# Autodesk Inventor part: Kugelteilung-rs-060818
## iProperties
Manager: Dr.-Ing. Roland Schröder
Company: www.Das-Entwicklungsbuero.de
Created: 2006-08
Part Number: Kugelteilung-rs-060818
Project: 11307
Document SubType Name: Modeling
Designer: rsc
Engineer: Dr.-Ing. Roland Schröder
Kanten: brechen
Oberflächen: Ra 6,4
Toleranzen: ISO 2768 - m
b: 30.000 mm
d: 30.000 mm
a: 30.000 mm
Author: rsc
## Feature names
1. Extrusion2
2. Extrusion3
3. Extrusion4
4. Drehung1 [Revolution]
5. Drehung2 [Revolution]
6. Trennen1
